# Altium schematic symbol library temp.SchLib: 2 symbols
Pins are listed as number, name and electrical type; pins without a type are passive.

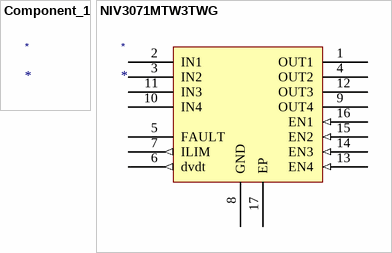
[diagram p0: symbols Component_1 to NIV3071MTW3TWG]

## Component_1
designator *

## NIV3071MTW3TWG
designator *
Electronic fuse (eFuse) 4-channel, 8V to 60V, 10A in 5x6mm package Latch version; Manufacturer: onsemi; Manufacturer Part Number: NIV3071MTW3TWG
footprint 16-WQFN-5x6
pins: 1 OUT1 (power), 2 IN1 (power), 3 IN2 (power), 4 OUT2 (power), 5 FAULT (oc), 6 dvdt (out), 7 ILIM (out), 8 GND, 9 OUT4 (power), 10 IN4 (power), 11 IN3 (power), 12 OUT3 (power), 13 EN4 (in), 14 EN3 (in), 15 EN2 (in), 16 EN1 (in), 17 EP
